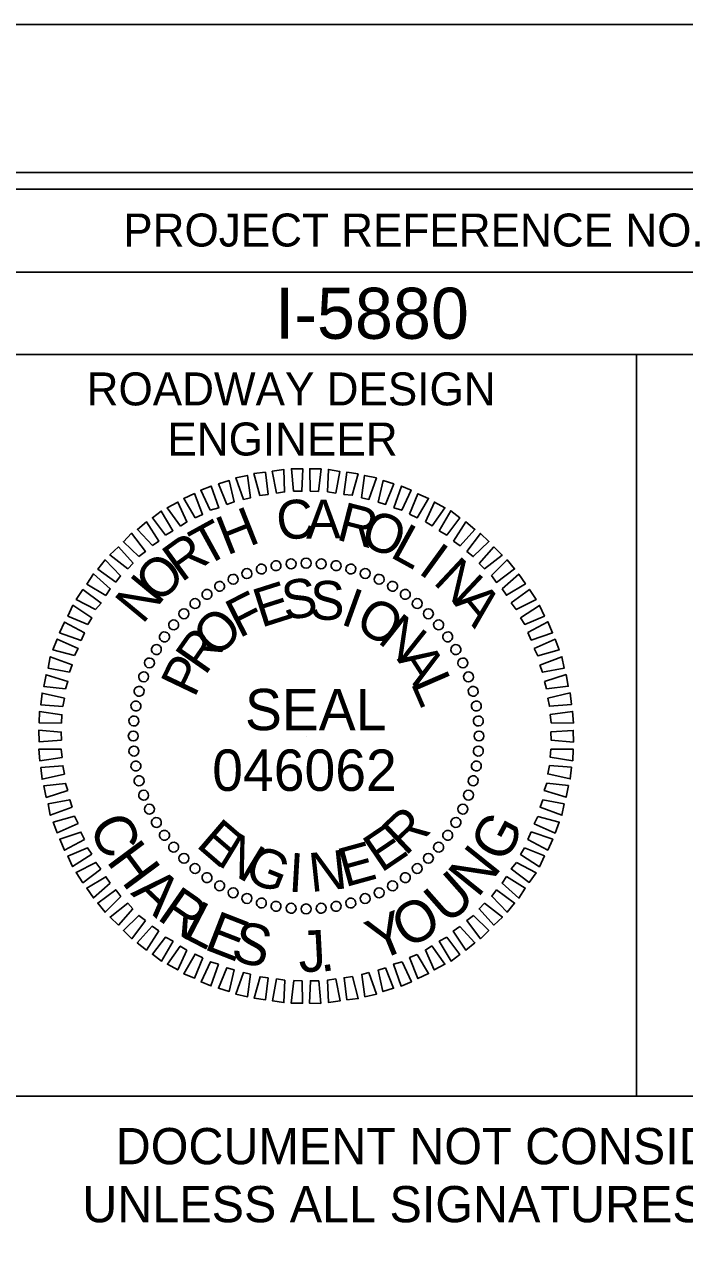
# Model space of a CAD drawing. Extents: x 1648862 to 1650855, y 808691 to 809791.
# Drawn here: x 1650336.5 to 1650436.6, y 809605.5 to 809791 of the extents above; entities that cross this region are included whole.
import ezdxf

# ---------------------------------------------------------------- set-up
doc = ezdxf.new("R2010")
doc.units = 0
for name, color, linetype in [('Default', 7, 'Continuous'), ('Old_Level_2', 7, 'Continuous'), ('Sheet Cutting Line CELL', 7, 'Continuous'), ('Sheet Data Field CELL', 7, 'Continuous'), ('Sheet Plot Border Inside CELL', 7, 'Continuous'), ('Sheet Plot Border Outside CELL', 7, 'Continuous'), ('Sheet Profile CELL', 7, 'Continuous'), ('Sheet Profile Grid Major CELL', 7, 'Continuous'), ('Sheet Sticker Exception Certification CELL', 7, 'Continuous')]:
    doc.layers.add(name, color=color, linetype=linetype)

msp = doc.modelspace()

# ---------------------------------------------------------------- linework, layer by layer
at = {"layer": 'Old_Level_2'}
for p, q in [((1650376.9, 809709.25), (1650376.9, 809709.25)), ((1650379.2, 809709.34), (1650379.2, 809709.34)), ((1650381.5, 809709.22), (1650381.5, 809709.22)), ((1650370.18, 809707.77), (1650370.18, 809707.77)), ((1650372.36, 809708.44), (1650372.36, 809708.44)), ((1650374.65, 809708.89), (1650374.65, 809708.89)), ((1650383.75, 809708.9), (1650383.75, 809708.9)), ((1650385.96, 809708.46), (1650385.96, 809708.46)), ((1650388.17, 809707.77), (1650388.17, 809707.77)), ((1650366.08, 809705.82), (1650366.08, 809705.82)), ((1650368.1, 809706.9), (1650368.1, 809706.9)), ((1650390.27, 809706.87), (1650390.27, 809706.87)), ((1650392.33, 809705.86), (1650392.33, 809705.86)), ((1650364.11, 809704.58), (1650364.11, 809704.58)), ((1650394.24, 809704.58), (1650394.24, 809704.58)), ((1650360.61, 809701.64), (1650360.61, 809701.64)), ((1650362.31, 809703.24), (1650362.31, 809703.24)), ((1650396.09, 809703.2), (1650396.09, 809703.2)), ((1650397.74, 809701.66), (1650397.74, 809701.66)), ((1650359.07, 809699.99), (1650359.07, 809699.99)), ((1650399.34, 809699.96), (1650399.34, 809699.96)), ((1650357.69, 809698.14), (1650357.69, 809698.14)), ((1650400.68, 809698.16), (1650400.68, 809698.16)), ((1650356.42, 809696.23), (1650356.42, 809696.23)), ((1650401.91, 809696.19), (1650401.91, 809696.19)), ((1650355.41, 809694.18), (1650355.41, 809694.18)), ((1650402.99, 809694.17), (1650402.99, 809694.17)), ((1650354.5, 809692.07), (1650354.5, 809692.07)), ((1650403.87, 809692.09), (1650403.87, 809692.09)), ((1650353.81, 809689.86), (1650353.81, 809689.86)), ((1650404.53, 809689.91), (1650404.53, 809689.91)), ((1650353.37, 809687.66), (1650353.37, 809687.66)), ((1650404.99, 809687.62), (1650404.99, 809687.62)), ((1650353.05, 809685.4), (1650353.05, 809685.4)), ((1650405.34, 809685.37), (1650405.34, 809685.37)), ((1650352.93, 809683.1), (1650352.93, 809683.1)), ((1650379.18, 809683.09), (1650379.18, 809683.09)), ((1650405.44, 809683.07), (1650405.44, 809683.07)), ((1650353.02, 809680.8), (1650353.02, 809680.8)), ((1650405.32, 809680.77), (1650405.32, 809680.77)), ((1650353.38, 809678.56), (1650353.38, 809678.56)), ((1650404.99, 809678.52), (1650404.99, 809678.52)), ((1650353.84, 809676.26), (1650353.84, 809676.26)), ((1650404.56, 809676.31), (1650404.56, 809676.31)), ((1650354.5, 809674.08), (1650354.5, 809674.08)), ((1650403.87, 809674.1), (1650403.87, 809674.1)), ((1650355.37, 809672), (1650355.37, 809672)), ((1650402.96, 809672), (1650402.96, 809672)), ((1650356.46, 809669.98), (1650356.46, 809669.98)), ((1650401.95, 809669.94), (1650401.95, 809669.94)), ((1650357.69, 809668.02), (1650357.69, 809668.02)), ((1650400.68, 809668.03), (1650400.68, 809668.03)), ((1650359.03, 809666.21), (1650359.03, 809666.21)), ((1650360.63, 809664.51), (1650360.63, 809664.51)), ((1650397.76, 809664.53), (1650397.76, 809664.53)), ((1650399.3, 809666.18), (1650399.3, 809666.18)), ((1650362.28, 809662.97), (1650362.28, 809662.97)), ((1650396.06, 809662.93), (1650396.06, 809662.93)), ((1650364.13, 809661.59), (1650364.13, 809661.59)), ((1650394.25, 809661.59), (1650394.25, 809661.59)), ((1650366.04, 809660.32), (1650366.04, 809660.32)), ((1650368.09, 809659.31), (1650368.09, 809659.31)), ((1650390.27, 809659.28), (1650390.27, 809659.28)), ((1650392.29, 809660.36), (1650392.29, 809660.36)), ((1650370.2, 809658.4), (1650370.2, 809658.4)), ((1650372.41, 809657.71), (1650372.41, 809657.71)), ((1650374.61, 809657.28), (1650374.61, 809657.28)), ((1650383.71, 809657.28), (1650383.71, 809657.28)), ((1650386.01, 809657.74), (1650386.01, 809657.74)), ((1650388.19, 809658.4), (1650388.19, 809658.4)), ((1650376.87, 809656.95), (1650376.87, 809656.95)), ((1650379.17, 809656.83), (1650379.17, 809656.83)), ((1650381.47, 809656.93), (1650381.47, 809656.93))]:
    msp.add_line(p, q, dxfattribs=at)
for points in [[(1650369.67, 809718.95), (1650368.51, 809722.23), (1650370.28, 809722.62), (1650370.76, 809719.23)], [(1650372.17, 809719.57), (1650371.27, 809722.9), (1650373, 809723.09), (1650373.42, 809719.75)], [(1650374.67, 809719.93), (1650374.04, 809723.26), (1650375.81, 809723.5), (1650375.92, 809720.11)], [(1650377.28, 809720.24), (1650376.96, 809723.63), (1650378.69, 809723.61), (1650378.54, 809720.21)], [(1650379.79, 809720.23), (1650379.73, 809723.63), (1650381.46, 809723.6), (1650381.05, 809720.2)], [(1650382.41, 809720.12), (1650382.56, 809723.52), (1650384.29, 809723.23), (1650383.67, 809719.93)], [(1650384.92, 809719.74), (1650385.34, 809723.1), (1650387.07, 809722.86), (1650386.18, 809719.61)], [(1650387.6, 809719.21), (1650388.06, 809722.62), (1650389.85, 809722.23), (1650388.7, 809718.97)], [(1650364.62, 809717.35), (1650363.21, 809720.36), (1650364.77, 809721.01), (1650365.92, 809717.68)], [(1650367.17, 809718.23), (1650365.91, 809721.34), (1650367.53, 809721.84), (1650368.26, 809718.61)], [(1650390.12, 809718.58), (1650390.85, 809721.83), (1650392.48, 809721.34), (1650391.23, 809718.23)], [(1650392.49, 809717.68), (1650393.64, 809720.99), (1650395.11, 809720.39), (1650393.7, 809717.33)], [(1650360.12, 809714.92), (1650358.13, 809717.71), (1650359.74, 809718.57), (1650361.1, 809715.56)], [(1650362.34, 809716.21), (1650360.62, 809719.11), (1650362.23, 809719.87), (1650363.48, 809716.7)], [(1650394.86, 809716.72), (1650396.11, 809719.83), (1650397.75, 809719.13), (1650396.02, 809716.17)], [(1650397.29, 809715.56), (1650398.65, 809718.57), (1650400.23, 809717.71), (1650398.29, 809714.95)], [(1650357.84, 809713.57), (1650355.86, 809716.2), (1650357.2, 809717.22), (1650358.98, 809714.22)], [(1650399.35, 809714.19), (1650401.13, 809717.25), (1650402.51, 809716.18), (1650400.51, 809713.58)], [(1650355.88, 809711.97), (1650353.59, 809714.44), (1650354.98, 809715.56), (1650356.86, 809712.66)], [(1650401.52, 809712.66), (1650403.41, 809715.57), (1650404.79, 809714.44), (1650402.53, 809711.94)], [(1650353.82, 809710.31), (1650351.48, 809712.57), (1650352.71, 809713.85), (1650354.8, 809711.06)], [(1650403.54, 809711.07), (1650405.63, 809713.83), (1650406.91, 809712.59), (1650404.54, 809710.3)], [(1650352.12, 809708.45), (1650349.42, 809710.55), (1650350.71, 809711.77), (1650352.94, 809709.3)], [(1650405.45, 809709.27), (1650407.66, 809711.77), (1650408.93, 809710.54), (1650406.25, 809708.45)], [(1650350.33, 809706.43), (1650347.57, 809708.42), (1650348.7, 809709.8), (1650351.04, 809707.38)], [(1650407.31, 809707.42), (1650409.68, 809709.82), (1650410.8, 809708.43), (1650408.06, 809706.39)], [(1650348.79, 809704.42), (1650345.94, 809706.14), (1650346.91, 809707.68), (1650349.46, 809705.42)], [(1650408.92, 809705.41), (1650411.44, 809707.65), (1650412.46, 809706.15), (1650409.56, 809704.43)], [(1650410.31, 809703.29), (1650413.05, 809705.33), (1650414.07, 809703.78), (1650411.06, 809702.26)], [(1650347.26, 809702.3), (1650344.31, 809703.81), (1650345.33, 809705.3), (1650348.08, 809703.25)], [(1650346.05, 809700.03), (1650343.04, 809701.28), (1650343.8, 809702.92), (1650346.66, 809701.03)], [(1650411.71, 809701.02), (1650414.61, 809702.9), (1650415.32, 809701.29), (1650412.36, 809700.03)], [(1650345.04, 809697.6), (1650341.78, 809698.75), (1650342.54, 809700.38), (1650345.55, 809698.76)], [(1650412.8, 809698.79), (1650415.86, 809700.41), (1650416.56, 809698.75), (1650413.34, 809697.65)], [(1650344.04, 809695.29), (1650340.78, 809696.17), (1650341.43, 809697.8), (1650344.59, 809696.39)], [(1650413.78, 809696.35), (1650416.95, 809697.76), (1650417.55, 809696.15), (1650414.32, 809695.26)], [(1650343.3, 809692.76), (1650340.04, 809693.39), (1650340.38, 809695.12), (1650343.7, 809693.87)], [(1650414.66, 809693.85), (1650417.99, 809695.11), (1650418.33, 809693.39), (1650415.05, 809692.76)], [(1650342.66, 809690.24), (1650339.41, 809690.6), (1650339.75, 809692.39), (1650343.06, 809691.35)], [(1650415.33, 809691.35), (1650418.61, 809692.4), (1650418.95, 809690.63), (1650415.67, 809690.26)], [(1650342.29, 809687.57), (1650338.94, 809687.82), (1650339.12, 809689.6), (1650342.53, 809688.83)], [(1650415.85, 809688.85), (1650419.23, 809689.64), (1650419.42, 809687.87), (1650416.08, 809687.6)], [(1650342.07, 809685.05), (1650338.67, 809685.1), (1650338.75, 809686.83), (1650342.15, 809686.31)], [(1650416.21, 809686.35), (1650419.6, 809686.82), (1650419.73, 809685.05), (1650416.33, 809685.09)], [(1650342.07, 809682.44), (1650338.67, 809682.22), (1650338.64, 809684), (1650342.04, 809683.69)], [(1650416.3, 809683.73), (1650419.7, 809683.95), (1650419.73, 809682.17), (1650416.33, 809682.48)], [(1650342.16, 809679.83), (1650338.77, 809679.35), (1650338.64, 809681.12), (1650342.04, 809681.08)], [(1650416.3, 809681.12), (1650419.7, 809681.07), (1650419.62, 809679.35), (1650416.21, 809679.86)], [(1650342.52, 809677.32), (1650339.14, 809676.53), (1650338.95, 809678.3), (1650342.29, 809678.57)], [(1650416.08, 809678.61), (1650419.43, 809678.35), (1650419.25, 809676.57), (1650415.84, 809677.35)], [(1650343.04, 809674.82), (1650339.76, 809673.77), (1650339.41, 809675.54), (1650342.7, 809675.91)], [(1650415.71, 809675.93), (1650418.96, 809675.57), (1650418.62, 809673.79), (1650415.31, 809674.83)], [(1650343.71, 809672.32), (1650340.38, 809671.06), (1650340.04, 809672.78), (1650343.32, 809673.41)], [(1650415.07, 809673.41), (1650418.32, 809672.79), (1650417.99, 809671.06), (1650414.67, 809672.31)], [(1650344.59, 809669.83), (1650341.42, 809668.41), (1650340.82, 809670.02), (1650344.04, 809670.92)], [(1650414.33, 809670.89), (1650417.59, 809670), (1650416.94, 809668.37), (1650413.78, 809669.78)], [(1650345.57, 809667.39), (1650342.51, 809665.76), (1650341.8, 809667.42), (1650345.03, 809668.53)], [(1650413.33, 809668.57), (1650416.59, 809667.42), (1650415.83, 809665.79), (1650412.82, 809667.41)], [(1650346.66, 809665.16), (1650343.76, 809663.28), (1650343.05, 809664.88), (1650346.01, 809666.14)], [(1650412.32, 809666.15), (1650415.33, 809664.89), (1650414.57, 809663.26), (1650411.71, 809665.14)], [(1650348.05, 809662.88), (1650345.32, 809660.84), (1650344.3, 809662.4), (1650347.3, 809663.91)], [(1650411.11, 809663.88), (1650414.06, 809662.36), (1650413.04, 809660.88), (1650410.29, 809662.92)], [(1650349.45, 809660.76), (1650346.93, 809658.52), (1650345.91, 809660.02), (1650348.81, 809661.74)], [(1650409.57, 809661.76), (1650412.43, 809660.03), (1650411.46, 809658.5), (1650408.91, 809660.75)], [(1650351.06, 809658.75), (1650348.69, 809656.35), (1650347.57, 809657.75), (1650350.31, 809659.78)], [(1650408.04, 809659.74), (1650410.8, 809657.75), (1650409.67, 809656.37), (1650407.33, 809658.79)], [(1650352.92, 809656.9), (1650350.71, 809654.4), (1650349.44, 809655.63), (1650352.12, 809657.72)], [(1650406.25, 809657.72), (1650408.95, 809655.63), (1650407.66, 809654.4), (1650405.42, 809656.87)], [(1650354.83, 809655.1), (1650352.74, 809652.35), (1650351.46, 809653.58), (1650353.83, 809655.87)], [(1650404.55, 809655.86), (1650406.89, 809653.6), (1650405.66, 809652.33), (1650403.57, 809655.12)], [(1650356.85, 809653.52), (1650354.96, 809650.61), (1650353.58, 809651.73), (1650355.84, 809654.23)], [(1650402.49, 809654.21), (1650404.78, 809651.74), (1650403.39, 809650.61), (1650401.51, 809653.51)], [(1650359.02, 809651.98), (1650357.24, 809648.92), (1650355.86, 809649.99), (1650357.86, 809652.59)], [(1650400.53, 809652.6), (1650402.51, 809649.97), (1650401.17, 809648.95), (1650399.39, 809651.96)], [(1650361.08, 809650.61), (1650359.72, 809647.6), (1650358.14, 809648.46), (1650360.08, 809651.22)], [(1650363.51, 809649.45), (1650362.25, 809646.34), (1650360.62, 809647.04), (1650362.35, 809650)], [(1650396.03, 809649.96), (1650397.75, 809647.06), (1650396.14, 809646.3), (1650394.88, 809649.47)], [(1650398.25, 809651.26), (1650400.24, 809648.47), (1650398.63, 809647.6), (1650397.27, 809650.61)], [(1650365.88, 809648.5), (1650364.73, 809645.18), (1650363.26, 809645.78), (1650364.67, 809648.84)], [(1650368.25, 809647.6), (1650367.52, 809644.34), (1650365.89, 809644.83), (1650367.14, 809647.94)], [(1650391.2, 809647.94), (1650392.46, 809644.83), (1650390.84, 809644.33), (1650390.11, 809647.56)], [(1650393.75, 809648.82), (1650395.16, 809645.82), (1650393.6, 809645.16), (1650392.44, 809648.49)], [(1650370.77, 809646.96), (1650370.3, 809643.55), (1650368.52, 809643.94), (1650369.67, 809647.2)], [(1650373.44, 809646.43), (1650373.03, 809643.08), (1650371.3, 809643.31), (1650372.19, 809646.57)], [(1650375.96, 809646.06), (1650375.81, 809642.65), (1650374.08, 809642.94), (1650374.7, 809646.24)], [(1650378.58, 809645.95), (1650378.64, 809642.55), (1650376.91, 809642.57), (1650377.32, 809645.98)], [(1650381.09, 809645.94), (1650381.41, 809642.54), (1650379.68, 809642.57), (1650379.83, 809645.97)], [(1650383.7, 809646.24), (1650384.33, 809642.91), (1650382.56, 809642.67), (1650382.45, 809646.07)], [(1650386.2, 809646.6), (1650387.1, 809643.27), (1650385.37, 809643.08), (1650384.95, 809646.42)], [(1650388.7, 809647.22), (1650389.86, 809643.95), (1650388.09, 809643.55), (1650387.61, 809646.94)]]:
    msp.add_lwpolyline(points, close=True, dxfattribs=at)
for centre, major_axis in [((1650372.4, 809708.42), (-0.195, 0.727)), ((1650374.63, 809708.92), (-0.131, 0.742)), ((1650376.9, 809709.21), (-0.066, 0.75)), ((1650379.18, 809709.31), (0, 0.753)), ((1650381.47, 809709.21), (0.066, 0.75)), ((1650383.74, 809708.92), (0.131, 0.742)), ((1650385.97, 809708.42), (0.195, 0.727)), ((1650368.1, 809706.86), (-0.318, 0.682)), ((1650370.21, 809707.73), (-0.258, 0.708)), ((1650388.15, 809707.73), (0.258, 0.708)), ((1650390.27, 809706.86), (0.318, 0.682)), ((1650364.14, 809704.57), (-0.432, 0.617)), ((1650366.07, 809705.8), (-0.376, 0.652)), ((1650392.3, 809705.8), (0.376, 0.652)), ((1650394.23, 809704.57), (0.432, 0.617)), ((1650362.33, 809703.18), (-0.484, 0.577)), ((1650396.04, 809703.18), (0.484, 0.577)), ((1650360.64, 809701.63), (-0.532, 0.532)), ((1650397.73, 809701.63), (0.532, 0.532)), ((1650359.09, 809699.95), (-0.577, 0.484)), ((1650399.28, 809699.95), (0.577, 0.484)), ((1650357.7, 809698.13), (-0.617, 0.432)), ((1650400.67, 809698.13), (0.617, 0.432)), ((1650356.47, 809696.2), (-0.652, 0.376)), ((1650401.9, 809696.2), (0.652, 0.376)), ((1650355.41, 809694.17), (-0.682, 0.318)), ((1650402.95, 809694.17), (0.682, 0.318)), ((1650354.54, 809692.06), (-0.708, 0.258)), ((1650403.83, 809692.06), (0.708, 0.258)), ((1650353.85, 809689.87), (-0.727, 0.195)), ((1650404.52, 809689.87), (0.727, 0.195)), ((1650353.36, 809687.64), (-0.742, 0.131)), ((1650405.01, 809687.64), (0.742, 0.131)), ((1650353.06, 809685.37), (-0.75, 0.066)), ((1650405.31, 809685.37), (0.75, 0.066)), ((1650352.96, 809683.09), (-0.753, 0)), ((1650405.41, 809683.09), (0.753, 0)), ((1650353.06, 809680.8), (-0.75, -0.066)), ((1650405.31, 809680.8), (0.75, -0.066)), ((1650353.36, 809678.53), (-0.742, -0.131)), ((1650405.01, 809678.53), (0.742, -0.131)), ((1650353.85, 809676.3), (-0.727, -0.195)), ((1650404.52, 809676.3), (0.727, -0.195)), ((1650354.54, 809674.12), (-0.708, -0.258)), ((1650403.83, 809674.12), (0.708, -0.258)), ((1650355.41, 809672), (-0.682, -0.318)), ((1650402.95, 809672), (0.682, -0.318)), ((1650356.47, 809669.97), (-0.652, -0.376)), ((1650401.9, 809669.97), (0.652, -0.376)), ((1650357.7, 809668.04), (-0.617, -0.432)), ((1650400.67, 809668.04), (0.617, -0.432)), ((1650359.09, 809666.23), (-0.577, -0.484)), ((1650399.28, 809666.23), (0.577, -0.484)), ((1650360.64, 809664.54), (-0.532, -0.532)), ((1650397.73, 809664.54), (0.532, -0.532)), ((1650362.33, 809662.99), (-0.484, -0.577)), ((1650396.04, 809662.99), (0.484, -0.577)), ((1650364.14, 809661.6), (-0.432, -0.617)), ((1650366.07, 809660.37), (-0.376, -0.652)), ((1650392.3, 809660.37), (0.376, -0.652)), ((1650394.23, 809661.6), (0.432, -0.617)), ((1650368.1, 809659.32), (-0.318, -0.682)), ((1650370.21, 809658.44), (-0.258, -0.708)), ((1650388.15, 809658.44), (0.258, -0.708)), ((1650390.27, 809659.32), (0.318, -0.682)), ((1650372.4, 809657.75), (-0.195, -0.727)), ((1650374.63, 809657.26), (-0.131, -0.742)), ((1650376.9, 809656.96), (-0.066, -0.75)), ((1650379.18, 809656.86), (0, -0.753)), ((1650381.47, 809656.96), (0.066, -0.75)), ((1650383.74, 809657.26), (0.131, -0.742)), ((1650385.97, 809657.75), (0.195, -0.727))]:
    msp.add_ellipse(centre, major_axis=major_axis, ratio=0.999708, dxfattribs=at)
at = {"layer": 'Sheet Cutting Line CELL'}
msp.add_line((1650546.28, 809791.02), (1648862.28, 809791.02), dxfattribs=at)
at = {"layer": 'Sheet Plot Border Inside CELL'}
msp.add_lwpolyline([(1648875.28, 808713.47), (1650541.78, 808713.47), (1650541.78, 809768.57), (1648875.28, 809768.57)], close=True, dxfattribs=at)
at = {"layer": 'Sheet Plot Border Outside CELL'}
msp.add_lwpolyline([(1648862.28, 808691.02), (1650546.28, 808691.02), (1650546.28, 809791.02), (1648862.28, 809791.02)], close=True, dxfattribs=at)
at = {"layer": 'Sheet Profile CELL'}
for p, q in [((1650329.23, 809753.47), (1650529.28, 809753.47)), ((1650429.28, 809740.97), (1650429.28, 809628.52))]:
    msp.add_line(p, q, dxfattribs=at)
for points in [[(1650529.28, 809766.02), (1649029.28, 809766.02), (1649029.28, 808716.02), (1650529.28, 808716.02)], [(1650329.23, 809766.02), (1650529.28, 809766.02), (1650529.28, 809740.97), (1650329.23, 809740.97)], [(1650329.23, 809740.97), (1650429.28, 809740.97), (1650429.28, 809628.47), (1650329.23, 809628.47)], [(1650429.28, 809740.97), (1650529.28, 809740.97), (1650529.28, 809628.47), (1650429.28, 809628.47)]]:
    msp.add_lwpolyline(points, close=True, dxfattribs=at)
at = {"layer": 'Sheet Profile Grid Major CELL'}
msp.add_lwpolyline([(1650279.23, 809738.96), (1650279.23, 809266.02), (1650329.23, 809266.02), (1650329.23, 809766.02), (1650355.53, 809766.02)], dxfattribs=at)
at = {"layer": 'Sheet Sticker Exception Certification CELL'}
msp.add_line((1650329.23, 809628.47), (1650529.27, 809628.47), dxfattribs=at)
msp.add_line((1650329.23, 809628.47), (1650529.27, 809628.47), dxfattribs=at)

# ---------------------------------------------------------------- texts
at = {"layer": 'Default'}
for s, rotation, p in [('C', 297.1999, (1650346.07, 809669.36)), ('G', 61.7998, (1650409.3, 809663.59)), ('H', 306.6436, (1650348.76, 809664.11)), ('N', 51.2288, (1650405.21, 809658.4)), ('A', 316.4834, (1650352.45, 809659.18)), ('U', 41.4347, (1650400.63, 809654.33)), ('R', 325.1961, (1650356.38, 809655.41)), ('L', 332.5683, (1650360.12, 809652.71)), ('O', 30.0413, (1650394.53, 809650.66)), ('E', 338.7525, (1650363.5, 809650.83)), ('Y', 22.2426, (1650390, 809648.88)), ('S', 345.7591, (1650367.55, 809649.16)), ('J', 3.0321, (1650378.14, 809647.23)), ('.', 8.214, (1650381.39, 809647.28))]:
    msp.add_text(s, height=6.27, rotation=rotation, dxfattribs=at).set_placement(p)
at = {"layer": 'Old_Level_2'}
for s, rotation, p in [('C', 7.2199, (1650375.06, 809712.67)), ('A', 0.0203, (1650379.18, 809713.05)), ('R', 345.6211, (1650383.58, 809712.92)), ('H', 21.6195, (1650367.15, 809710.44)), ('O', 338.4212, (1650387.1, 809712.2)), ('T', 28.8198, (1650363.78, 809708.65)), ('L', 331.2209, (1650391.73, 809710.34)), ('R', 36.0205, (1650360.27, 809706.29)), ('I', 324.0201, (1650396.01, 809707.91)), ('O', 43.2217, (1650356.72, 809702.99)), ('N', 316.8189, (1650398.29, 809706.33)), ('N', 50.4235, (1650354.36, 809699.91)), ('E', 17.6111, (1650372.36, 809699.49)), ('S', 8.2556, (1650375.95, 809700.65)), ('S', 358.9004, (1650379.71, 809700.77)), ('I', 340.1896, (1650384.22, 809700.12)), ('A', 309.6172, (1650401.42, 809703.29)), ('F', 26.967, (1650369.04, 809697.87)), ('O', 330.8335, (1650386.33, 809699.42)), ('O', 45.6812, (1650365.65, 809694.72)), ('N', 321.4766, (1650389.86, 809697.39)), ('R', 55.0397, (1650363.86, 809692.13)), ('A', 302.7603, (1650392.89, 809694.73)), ('P', 64.3989, (1650362.25, 809688.75)), ('L', 293.4009, (1650394.99, 809691.15)), ('R', 43.4814, (1650394.25, 809664.78)), ('E', 319.2769, (1650362.32, 809666.42)), ('N', 328.634, (1650365.51, 809663.65)), ('E', 34.1241, (1650390.58, 809662.26)), ('E', 15.4118, (1650385.08, 809660.13)), ('G', 337.9902, (1650369.52, 809661.37)), ('I', 356.7012, (1650376.41, 809659.5)), ('N', 6.0564, (1650379.91, 809659.41))]:
    msp.add_text(s, height=5.9, rotation=rotation, dxfattribs=at).set_placement(p)
for s, height, p in [('SEAL', 6.273, (1650369.91, 809683.97)), ('046062', 6.275, (1650364.94, 809674.77))]:
    msp.add_text(s, height=height, dxfattribs=at).set_placement(p)
at = {"layer": 'Sheet Data Field CELL'}
msp.add_text('I-5880', height=7.75, dxfattribs=at).set_placement((1650374.49, 809743.34))
at = {"layer": 'Sheet Profile CELL'}
for s, height, p in [('PROJECT REFERENCE NO.', 5.0001, (1650351.44, 809757.34)), ('ROADWAY DESIGN', 5.0001, (1650345.89, 809733.24)), ('ENGINEER', 5, (1650358.14, 809725.64))]:
    msp.add_text(s, height=height, dxfattribs=at).set_placement(p)
at = {"layer": 'Sheet Sticker Exception Certification CELL'}
for s, p in [('DOCUMENT NOT CONSIDERED FINAL', (1650350.3, 809618.13)), ('DOCUMENT NOT CONSIDERED FINAL', (1650350.3, 809618.13)), ('UNLESS ALL SIGNATURES COMPLETED', (1650345.23, 809609.33)), ('UNLESS ALL SIGNATURES COMPLETED', (1650345.23, 809609.33))]:
    msp.add_text(s, height=5.5, dxfattribs=at).set_placement(p)

doc.saveas('drawing.dxf')
